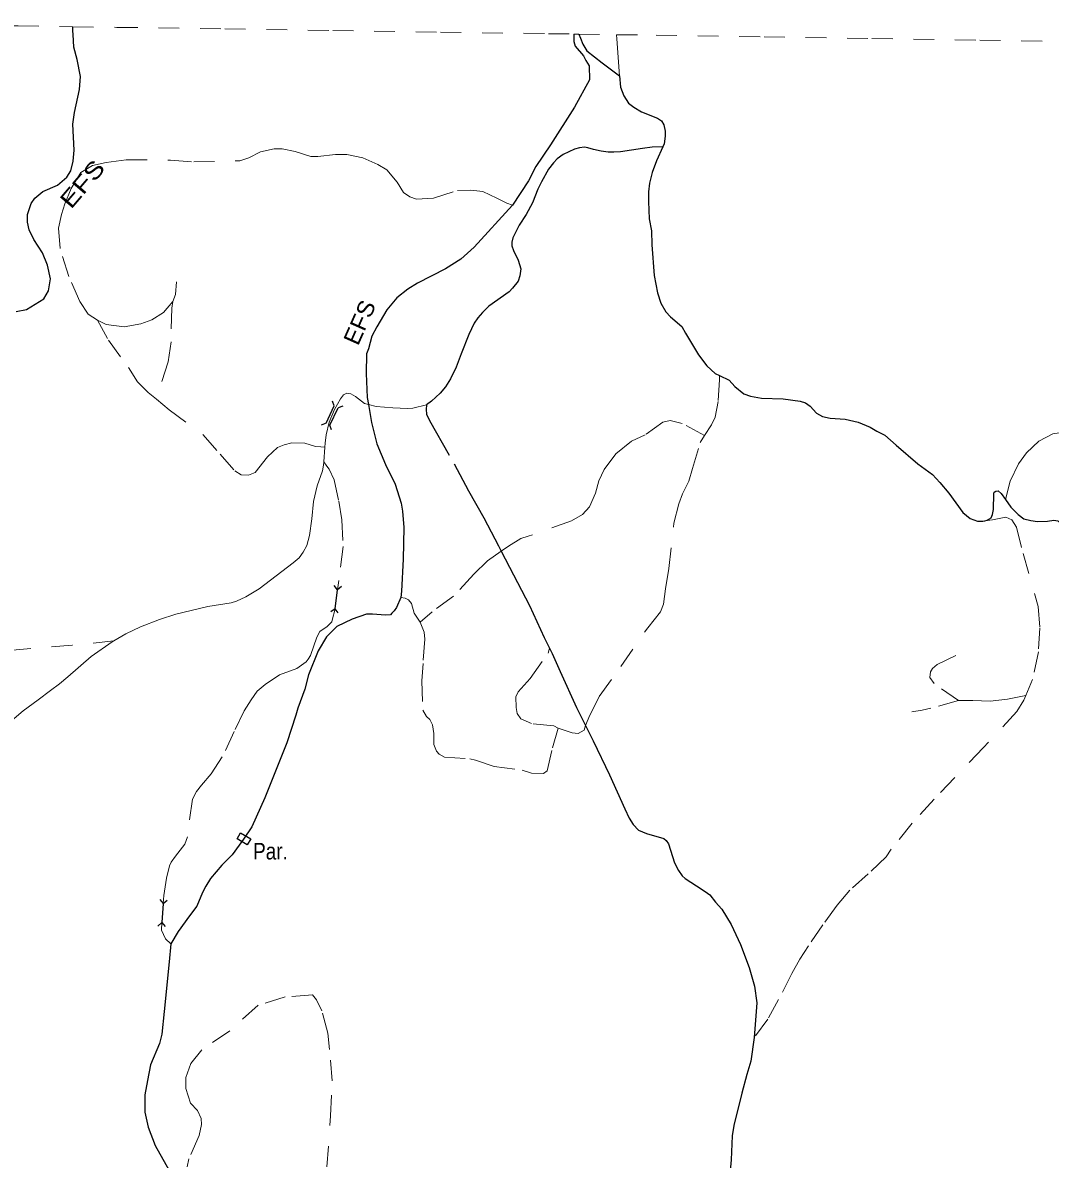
# Model space of a CAD drawing. Extents: x 703.1 to 728.9, y 7316.2 to 7344.3.
# Drawn here: x 709.23 to 714.18, y 7338.75 to 7344.23 of the extents above; entities that cross this region are included whole.
import ezdxf
from ezdxf.enums import TextEntityAlignment as Align

# ---------------------------------------------------------------- set-up
doc = ezdxf.new("R2010")
doc.units = 0
doc.header["$LTSCALE"] = 0.032
for name, pattern in [('DOTTED', [1.5, 0.3, -1.2]), ('LONG_DASHED', [7.5, 6, -1.5]), ('MEDIUM_DASHED', [4.5, 3, -1.5]), ('SHORT_DASHED', [2.7, 1.5, -1.2])]:
    doc.linetypes.add(name, pattern=pattern)
for name, color, linetype, lineweight in [('10', 7, 'Continuous', 25), ('15', 7, 'Continuous', 25), ('28', 7, 'Continuous', 25), ('31', 7, 'Continuous', 25), ('4', 7, 'LONG_DASHED', 25), ('5', 7, 'LONG_DASHED', 13), ('58', 7, 'SHORT_DASHED', 13), ('6', 7, 'MEDIUM_DASHED', 13), ('7', 7, 'DOTTED', 13)]:
    doc.layers.add(name, color=color, linetype=linetype, lineweight=lineweight)
doc.layers.add('61', color=7, linetype='Continuous')

msp = doc.modelspace()

# ---------------------------------------------------------------- linework, layer by layer
at = {"layer": '10'}
for p, q in [((710.7128, 7342.2886), (710.7526, 7342.3721)), ((710.7761, 7342.3805), (710.7526, 7342.3721)), ((710.6948, 7342.2972), (710.6713, 7342.289)), ((710.7212, 7342.2652), (710.7128, 7342.2886))]:
    msp.add_line(p, q, dxfattribs=at)
msp.add_lwpolyline([(710.6948, 7342.2972), (710.7345, 7342.3807), (710.7261, 7342.4043)], dxfattribs=at)
at = {"layer": '15'}
for points in [[(709.2657, 7343.2281), (709.2573, 7343.2656), (709.2573, 7343.3032), (709.2746, 7343.3548), (709.2923, 7343.3809), (709.3308, 7343.4132), (709.4017, 7343.4445), (709.4466, 7343.482), (709.4664, 7343.5123), (709.4778, 7343.5592), (709.482, 7343.6124), (709.4763, 7343.7371), (709.4836, 7343.7934), (709.5086, 7343.904), (709.5133, 7343.9671), (709.4967, 7344.0484), (709.48, 7344.1089), (709.4769, 7344.1694), (709.4766, 7344.1867), (709.4762, 7344.2067)], [(711.8886, 7344.1713), (711.8872, 7344.1351), (711.8935, 7344.1124), (711.9338, 7344.0658), (711.9464, 7344.0444), (711.9615, 7344.018), (711.9628, 7343.9512), (711.891, 7343.819), (711.7752, 7343.6376), (711.7053, 7343.5337), (711.67, 7343.4645), (711.593, 7343.3479)], [(711.593, 7343.3479), (711.4074, 7343.1458), (711.3438, 7343.0873), (711.2708, 7343.0407), (711.1348, 7342.9714), (711.0882, 7342.9437), (711.0353, 7342.9021), (710.9875, 7342.8442), (710.9391, 7342.7618), (710.9152, 7342.7164), (710.8988, 7342.656), (710.89, 7342.632), (710.8875, 7342.5363), (710.8931, 7342.4211), (710.8987, 7342.3882)], [(709.3361, 7342.8958), (709.359, 7342.9355), (709.3689, 7342.9923), (709.3543, 7343.0591), (709.3303, 7343.1185), (709.2886, 7343.1822), (709.2657, 7343.2281)], [(709.2026, 7342.8353), (709.2527, 7342.8447), (709.3361, 7342.8958)], [(710.8987, 7342.3882), (710.9133, 7342.3015), (710.9391, 7342.1988), (710.9806, 7342.0993), (711.0272, 7342.0048), (711.0567, 7341.9123), (711.063, 7341.8745), (711.0693, 7341.7951), (711.0668, 7341.6428), (711.0587, 7341.4885), (711.0545, 7341.4582)], [(711.0545, 7341.4582), (711.0347, 7341.4104), (711.0222, 7341.394), (711.0121, 7341.3839), (711.0045, 7341.3751), (710.9819, 7341.3739), (710.9189, 7341.3789), (710.89, 7341.3776), (710.8207, 7341.355), (710.7465, 7341.3197), (710.6967, 7341.2686), (710.6564, 7341.2019), (710.6099, 7341.086), (710.5922, 7341.0167), (710.5589, 7340.9254), (710.5488, 7340.8927), (710.506, 7340.7592), (710.3997, 7340.494), (710.3373, 7340.3549), (710.2983, 7340.2944), (710.2429, 7340.2189), (710.1932, 7340.1691), (710.1391, 7340.1049), (710.1164, 7340.0683), (710.1001, 7340.0381), (710.0724, 7339.9726), (710.0371, 7339.926), (709.9824, 7339.8499), (709.9477, 7339.7909)], [(709.9477, 7339.7909), (709.9396, 7339.7038), (709.9163, 7339.4651), (709.9043, 7339.3561), (709.893, 7339.312), (709.8502, 7339.2087), (709.8351, 7339.1332), (709.8231, 7339.0645), (709.8231, 7338.9814), (709.8382, 7338.9083), (709.8722, 7338.8202), (709.9672, 7338.652)]]:
    msp.add_lwpolyline(points, dxfattribs=at)
at = {"layer": '28'}
msp.add_lwpolyline([(710.3154, 7340.2675), (710.2664, 7340.2966), (710.2837, 7340.3258), (710.3328, 7340.2967)], close=True, dxfattribs=at)
at = {"layer": '31'}
for p, q in [((710.7497, 7341.4959), (710.7343, 7341.5156)), ((710.7385, 7341.4041), (710.7497, 7341.4959)), ((710.7693, 7341.5113), (710.7497, 7341.4959)), ((710.7385, 7341.4041), (710.7188, 7341.3888)), ((710.7538, 7341.3846), (710.7385, 7341.4041)), ((709.8943, 7340.0042), (709.9106, 7339.9855)), ((709.9106, 7339.9855), (709.9038, 7339.8932)), ((709.9106, 7339.9855), (709.9295, 7340.0016)), ((709.8849, 7339.8769), (709.9038, 7339.8932)), ((709.9038, 7339.8932), (709.9201, 7339.8743))]:
    msp.add_line(p, q, dxfattribs=at)
at = {"layer": '4'}
for points in [[(711.9116, 7344.171), (711.9195, 7344.1509), (711.9306, 7344.1229), (711.9503, 7344.0912), (712.0238, 7344.0328), (712.1082, 7343.97)], [(712.1082, 7343.97), (712.112, 7343.9161), (712.1281, 7343.8735), (712.151, 7343.8386), (712.1763, 7343.819), (712.2144, 7343.7961), (712.2911, 7343.7663), (712.3092, 7343.753), (712.3219, 7343.734), (712.3276, 7343.7042), (712.3283, 7343.6801), (712.3235, 7343.6432), (712.3171, 7343.6286)], [(712.3171, 7343.6286), (712.2645, 7343.6267), (712.2188, 7343.6198), (712.1123, 7343.6045), (712.0809, 7343.6026), (712.0536, 7343.6033), (712.0187, 7343.6077), (711.9832, 7343.616), (711.9559, 7343.6236), (711.9388, 7343.6268), (711.9147, 7343.623), (711.8906, 7343.6166), (711.8373, 7343.5912), (711.8078, 7343.5709), (711.79, 7343.5506), (711.7665, 7343.5202), (711.7316, 7343.4593), (711.7139, 7343.425), (711.6882, 7343.3584), (711.6577, 7343.3026), (711.6254, 7343.2518), (711.594, 7343.1897), (711.5895, 7343.1694), (711.5895, 7343.151), (711.5971, 7343.1294), (711.6206, 7343.0831), (711.6323, 7343.0412), (711.6285, 7343.0075), (711.6196, 7342.9815), (711.593, 7342.9479), (711.5765, 7342.9308), (711.4791, 7342.861), (711.448, 7342.8305), (711.4252, 7342.8045), (711.4087, 7342.7791), (711.3817, 7342.7246), (711.3455, 7342.6313), (711.3218, 7342.5673), (711.2939, 7342.5121), (711.2701, 7342.4733), (711.2441, 7342.4423), (711.2022, 7342.4042), (711.1787, 7342.3858)], [(712.3171, 7343.6286), (712.2851, 7343.5604), (712.2644, 7343.5055), (712.2528, 7343.4531), (712.247, 7343.4124), (712.2473, 7343.3646), (712.2505, 7343.2824), (712.2619, 7343.2236), (712.2638, 7343.157), (712.2744, 7343.0096), (712.2903, 7342.9249), (712.3064, 7342.8751), (712.3307, 7342.8344), (712.3527, 7342.8092), (712.407, 7342.7626), (712.4257, 7342.7316), (712.4874, 7342.6262), (712.5284, 7342.5739), (712.5684, 7342.5377), (712.5899, 7342.5273)], [(712.5899, 7342.5273), (712.6357, 7342.5053), (712.6628, 7342.475), (712.7061, 7342.4394), (712.7391, 7342.4278), (712.7908, 7342.4187), (712.8958, 7342.4155), (712.9772, 7342.4032), (713.0024, 7342.3954), (713.0263, 7342.3793), (713.0554, 7342.3456), (713.0849, 7342.3294), (713.1211, 7342.3223), (713.1947, 7342.3178), (713.2561, 7342.3029), (713.3143, 7342.2784), (713.3463, 7342.259), (713.3851, 7342.2396), (713.4401, 7342.1918), (713.5435, 7342.1019), (713.6149, 7342.0502), (713.6504, 7342.0127), (713.6924, 7341.9616), (713.7613, 7341.8672), (713.7955, 7341.8388), (713.8304, 7341.8265), (713.8576, 7341.8265), (713.8671, 7341.8284)], [(711.1787, 7342.3858), (711.1765, 7342.3642), (711.1778, 7342.3413), (711.1924, 7342.3109), (711.3113, 7342.1027), (711.3814, 7341.9727), (711.4553, 7341.8419), (711.5248, 7341.7068), (711.5381, 7341.6812)], [(713.8671, 7341.8284), (713.877, 7341.8304), (713.8854, 7341.8349), (713.8967, 7341.8427), (713.9031, 7341.8575), (713.9089, 7341.8815), (713.9096, 7341.9577), (713.9115, 7341.9655), (713.9199, 7341.9713), (713.9303, 7341.972), (713.9451, 7341.959), (713.9656, 7341.9306)], [(713.9656, 7341.9306), (713.9923, 7341.8937), (714.0266, 7341.8582), (714.0544, 7341.8381), (714.088, 7341.8297), (714.1196, 7341.8252), (714.1681, 7341.8265), (714.1982, 7341.831), (714.2176, 7341.8271), (714.2318, 7341.8142)], [(711.5381, 7341.6812), (711.5975, 7341.5673), (711.6751, 7341.4207), (711.7446, 7341.2665), (711.7709, 7341.214)], [(711.7709, 7341.214), (711.7837, 7341.1884), (711.8223, 7341.1015), (711.9, 7340.9295), (711.9439, 7340.8421)], [(711.9439, 7340.8421), (711.9809, 7340.7684), (712.0593, 7340.6053), (712.1331, 7340.4409), (712.1538, 7340.3965), (712.1728, 7340.3654), (712.1988, 7340.3382), (712.2369, 7340.3223), (712.3212, 7340.2988), (712.3323, 7340.2887), (712.3431, 7340.2722), (712.3723, 7340.1815), (712.3923, 7340.1434), (712.4101, 7340.118), (712.424, 7340.1053), (712.478, 7340.071), (712.5205, 7340.0438), (712.5433, 7340.0273), (712.5696, 7339.9924), (712.6, 7339.9575), (712.6457, 7339.8845), (712.6904, 7339.7886), (712.7313, 7339.6776), (712.7569, 7339.5869), (712.7684, 7339.5076), (712.7566, 7339.3395)], [(712.7566, 7339.3395), (712.7398, 7339.2266), (712.7211, 7339.1613), (712.697, 7339.0718), (712.6574, 7338.9158), (712.6508, 7338.8663), (712.6451, 7338.7508), (712.6295, 7338.575), (712.6178, 7338.4067)]]:
    msp.add_lwpolyline(points, dxfattribs=at)
at = {"layer": '5'}
for points in [[(712.1082, 7343.97), (712.0952, 7344.1482), (712.0937, 7344.1682)], [(710.8987, 7342.3882), (710.8803, 7342.3927), (710.8362, 7342.4269), (710.8135, 7342.4392), (710.7954, 7342.4423), (710.7785, 7342.4346), (710.7647, 7342.4146), (710.7358, 7342.3634), (710.7104, 7342.3026), (710.6956, 7342.2411), (710.691, 7342.2018), (710.6895, 7342.1817), (710.6844, 7342.1114)], [(711.1787, 7342.3858), (711.1122, 7342.3707), (711.0865, 7342.3684), (711.0164, 7342.3711), (710.9368, 7342.3788), (710.8987, 7342.3882)], [(710.6844, 7342.1114), (710.6832, 7342.0953), (710.678, 7342.0687), (710.653, 7341.9967), (710.6345, 7341.9202), (710.6261, 7341.837), (710.6155, 7341.7566), (710.6026, 7341.7097), (710.5853, 7341.677), (710.5653, 7341.6497), (710.537, 7341.6262), (710.4281, 7341.5415), (710.3726, 7341.5008), (710.3087, 7341.4615), (710.2637, 7341.4411), (710.2386, 7341.4323), (710.1266, 7341.4154), (709.9711, 7341.3776), (709.8924, 7341.353), (709.8016, 7341.318), (709.7315, 7341.283), (709.6726, 7341.2493)], [(709.6726, 7341.2493), (709.6649, 7341.2449), (709.5644, 7341.1738), (709.4511, 7341.0768), (709.412, 7341.0437), (709.3685, 7341.0102), (709.3089, 7340.9663), (709.2361, 7340.9125), (709.1718, 7340.8571)]]:
    msp.add_lwpolyline(points, dxfattribs=at)
at = {"layer": '58'}
for points in [[(708.1672, 7344.2258), (708.6502, 7344.2188), (709.1693, 7344.2112), (709.2122, 7344.2106), (709.4762, 7344.2067)], [(709.4762, 7344.2067), (709.6885, 7344.2036), (710.2077, 7344.196), (710.7269, 7344.1884), (711.2461, 7344.1807), (711.7653, 7344.1731), (711.8886, 7344.1713), (711.9116, 7344.171), (712.0937, 7344.1682)], [(712.0937, 7344.1682), (712.2844, 7344.1654), (712.8036, 7344.1577), (713.3228, 7344.15), (713.842, 7344.1422), (714.3612, 7344.1345), (714.5271, 7344.132)]]:
    msp.add_lwpolyline(points, dxfattribs=at)
at = {"layer": '6'}
for p, q in [((710.7497, 7341.4959), (710.7385, 7341.4041)), ((710.7385, 7341.4041), (710.7245, 7341.3501))]:
    msp.add_line(p, q, dxfattribs=at)
for points in [[(712.5899, 7342.5273), (712.5887, 7342.5073), (712.5823, 7342.4022), (712.569, 7342.3274), (712.5505, 7342.2904), (712.5167, 7342.2392)], [(712.5167, 7342.2392), (712.4101, 7342.2966), (712.3517, 7342.3109), (712.3169, 7342.3027), (712.2308, 7342.2412), (712.1652, 7342.2105), (712.0894, 7342.15), (712.0331, 7342.0752), (712.0079, 7342.0198), (711.9916, 7341.9604), (711.9629, 7341.8958), (711.929, 7341.8589), (711.8768, 7341.8282), (711.6682, 7341.7534), (711.6334, 7341.7431), (711.574, 7341.7062), (711.5381, 7341.6812)], [(711.9439, 7340.8421), (711.9654, 7340.8913), (712.0105, 7340.9815), (712.114, 7341.1271), (712.2436, 7341.3126), (712.3045, 7341.3895), (712.3189, 7341.4264), (712.3291, 7341.5002), (712.3455, 7341.5986), (712.3696, 7341.8169), (712.3937, 7341.9102), (712.4111, 7341.9584), (712.4419, 7342.0188), (712.4593, 7342.0803), (712.4967, 7342.2043), (712.5167, 7342.2392)], [(710.6844, 7342.1114), (710.699, 7342.0913), (710.7103, 7342.0757), (710.7348, 7342.0258), (710.7566, 7341.9222), (710.7711, 7341.8323), (710.777, 7341.7034), (710.7558, 7341.5404), (710.7497, 7341.4959)], [(713.8671, 7341.8284), (713.9029, 7341.8322), (713.9683, 7341.8461), (713.996, 7341.8322), (714.0188, 7341.7965), (714.0515, 7341.6697), (714.1228, 7341.4149), (714.1312, 7341.3114), (714.1243, 7341.1964), (714.0961, 7341.0631), (714.0639, 7340.9863)], [(711.5381, 7341.6812), (711.4725, 7341.6355), (711.4065, 7341.5709), (711.3081, 7341.4643), (711.2061, 7341.3895), (711.1477, 7341.3403)], [(711.1477, 7341.3403), (711.119, 7341.3833), (711.1057, 7341.4295), (711.0914, 7341.4479), (711.076, 7341.4561), (711.0545, 7341.4582)], [(710.7245, 7341.3501), (710.7225, 7341.3419), (710.7007, 7341.3183), (710.6644, 7341.2956), (710.6499, 7341.2675), (710.6195, 7341.1794), (710.6095, 7341.1621), (710.5986, 7341.1494), (710.555, 7341.1167), (710.4715, 7341.0858), (710.4016, 7341.0395), (710.3635, 7341.0068), (710.334, 7340.9651), (710.3004, 7340.9133), (710.2523, 7340.8134), (710.1956, 7340.6908), (710.142, 7340.61), (710.0957, 7340.5546), (710.0716, 7340.5247), (710.0517, 7340.4874), (710.0272, 7340.3067), (710.0159, 7340.2713), (709.9705, 7340.2132), (709.9487, 7340.1851), (709.9414, 7340.166), (709.9269, 7340.1079), (709.9144, 7340.0231), (709.9106, 7339.9855), (709.9038, 7339.8932)], [(711.1477, 7341.3403), (711.1672, 7341.2921), (711.1703, 7341.2572), (711.1621, 7341.1404), (711.1564, 7341.0574), (711.1615, 7340.9159), (711.1779, 7340.8852), (711.1943, 7340.8708), (711.2072, 7340.8462), (711.2143, 7340.8031), (711.2133, 7340.7509), (711.2266, 7340.7181), (711.2399, 7340.7037), (711.2656, 7340.6894), (711.3865, 7340.6822), (711.4141, 7340.675), (711.5043, 7340.6443), (711.6396, 7340.6268), (711.6841, 7340.6124), (711.7425, 7340.6114), (711.7599, 7340.6247), (711.7856, 7340.7344), (711.8132, 7340.8298)], [(709.6726, 7341.2493), (709.4726, 7341.2292), (709.1861, 7341.205), (709.0925, 7341.1978), (708.9143, 7341.1512), (708.8149, 7341.1387), (708.724, 7341.1261), (708.6658, 7341.1369), (708.5601, 7341.1825), (708.4809, 7341.2247), (708.4074, 7341.2479), (708.36, 7341.2417), (708.3053, 7341.2238), (708.2534, 7341.1799)], [(711.8132, 7340.8298), (711.7911, 7340.84), (711.6845, 7340.8515), (711.6333, 7340.8745), (711.6156, 7340.9006), (711.6104, 7340.9288), (711.6093, 7340.9811), (711.6198, 7341.0051), (711.6783, 7341.0679), (711.7639, 7341.1912), (711.7709, 7341.214)], [(714.0639, 7340.9863), (714.0545, 7340.964), (714.0203, 7340.91), (713.8608, 7340.7366), (713.623, 7340.4878), (713.516, 7340.3718), (713.4159, 7340.2469), (713.3916, 7340.2098), (713.3044, 7340.1275), (713.2163, 7340.0492), (713.1548, 7339.9769), (713.0869, 7339.8832), (713.0176, 7339.7811), (712.9765, 7339.7172), (712.9378, 7339.6478), (712.8735, 7339.523), (712.8215, 7339.4283), (712.7566, 7339.3395)], [(711.8132, 7340.8298), (711.8804, 7340.8062), (711.9091, 7340.8042), (711.9377, 7340.8195), (711.9439, 7340.8421)], [(709.9477, 7339.7909), (709.9214, 7339.8154), (709.9028, 7339.8572), (709.9038, 7339.8932)], [(710.6989, 7338.7173), (710.7165, 7338.9628), (710.7248, 7339.1319), (710.7116, 7339.2816), (710.7033, 7339.3614), (710.6747, 7339.4693), (710.6494, 7339.5221), (710.6296, 7339.5463), (710.4975, 7339.5353), (710.3677, 7339.4957), (710.2312, 7339.3724), (710.0964, 7339.2815), (710.0447, 7339.2155), (710.0194, 7339.1483), (710.02, 7339.0949), (710.042, 7339.0244), (710.0761, 7338.9892), (710.0937, 7338.9496), (710.0959, 7338.9209), (710.0838, 7338.8681), (710.0349, 7338.7563), (710.0261, 7338.7178)]]:
    msp.add_lwpolyline(points, dxfattribs=at)
at = {"layer": '7'}
for points in [[(709.5943, 7342.7936), (709.5495, 7342.8231), (709.5095, 7342.8831), (709.4565, 7343.0045), (709.4147, 7343.1393), (709.4065, 7343.2371), (709.4212, 7343.3025), (709.4377, 7343.3544), (709.4683, 7343.4274), (709.5142, 7343.504), (709.5708, 7343.5381), (709.6367, 7343.5535), (709.7332, 7343.5652), (709.9469, 7343.5647), (710.0581, 7343.5558), (710.2795, 7343.5606), (710.3231, 7343.5747), (710.3796, 7343.6041), (710.4455, 7343.6183), (710.4844, 7343.6183), (710.5468, 7343.6053), (710.6221, 7343.5818), (710.6557, 7343.5812), (710.7404, 7343.5906), (710.7946, 7343.5906), (710.8723, 7343.5753), (710.9441, 7343.5435), (710.9877, 7343.5175), (711.0366, 7343.4581), (711.0684, 7343.4086), (711.099, 7343.3874), (711.1308, 7343.3768), (711.212, 7343.3815), (711.3286, 7343.418), (711.3922, 7343.4204), (711.4505, 7343.4127), (711.5176, 7343.3809), (711.5647, 7343.3573), (711.593, 7343.3479)], [(709.9746, 7342.9786), (709.971, 7342.9173), (709.9569, 7342.8831)], [(709.9569, 7342.8831), (709.9122, 7342.8313), (709.8557, 7342.7948), (709.8038, 7342.7759), (709.7238, 7342.7618), (709.6366, 7342.7736), (709.5943, 7342.7936)], [(709.9569, 7342.8831), (709.9522, 7342.8513), (709.9487, 7342.6888), (709.9345, 7342.5933), (709.878, 7342.4131)], [(709.5943, 7342.7936), (709.6472, 7342.6982), (709.7438, 7342.5651), (709.7874, 7342.4967), (709.8392, 7342.4449), (709.878, 7342.4131)], [(709.878, 7342.4131), (709.9402, 7342.3621), (710.104, 7342.2413), (710.1847, 7342.1488), (710.2557, 7342.0684), (710.2862, 7342.0488), (710.3215, 7342.0472), (710.3536, 7342.0605), (710.4124, 7342.135), (710.4618, 7342.1805), (710.4936, 7342.1935), (710.5296, 7342.2029), (710.5923, 7342.2013), (710.6441, 7342.1856), (710.6695, 7342.1834), (710.6895, 7342.1817)], [(713.9656, 7341.9306), (713.9891, 7342.0191), (714.0278, 7342.1015), (714.0676, 7342.1558), (714.1267, 7342.212), (714.1945, 7342.2469), (714.2555, 7342.2566), (714.3243, 7342.2614), (714.3979, 7342.2547), (714.4928, 7342.2265), (714.5355, 7342.213), (714.612, 7342.211)], [(713.7394, 7340.9619), (713.623, 7341.0441), (713.6013, 7341.073), (713.6049, 7341.101), (713.6139, 7341.1163), (713.6365, 7341.1353), (713.7268, 7341.1787)], [(713.7394, 7340.9619), (713.6058, 7340.9258), (713.5643, 7340.9158), (713.5155, 7340.9086)], [(714.0639, 7340.9863), (713.975, 7340.9691), (713.892, 7340.9601), (713.8089, 7340.9619), (713.7394, 7340.9619)]]:
    msp.add_lwpolyline(points, dxfattribs=at)

# ---------------------------------------------------------------- texts
at = {"layer": '61'}
for rotation, width, p in [(49.477, 1.25, (709.5521, 7343.4237)), (66.085, 1.05, (710.8932, 7342.7668))]:
    msp.add_text('EFS', height=0.08, rotation=rotation, dxfattribs=dict(at, width=width)).set_placement(p, align=Align.CENTER)
at = {"layer": '61', "width": 0.85}
msp.add_text('Par.', height=0.08, dxfattribs=at).set_placement((710.3439, 7340.1972))

doc.saveas('drawing.dxf')
